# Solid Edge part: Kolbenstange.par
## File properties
Username: bmolnar
Dokumentum tartalom típus: 0
Author: bmolnar
Last saved by: bmolnar
Revision: 77
Sűrűség: 0,000 kg/m^3
Pontosság: 0,990
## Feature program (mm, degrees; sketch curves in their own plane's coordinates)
base feature "unnamed BaseFeature 1"
sketch for "unnamed Protrusion 1" plane through (30, 0, 0) normal (1, 0, 0) x-axis (0, -1, 0)
  circle centre (0, 0) radius 31.5
extrude "unnamed Protrusion 1" add finite 18.25 along +normal
sketch for "Kihúzás_2" plane through (30, 0, 0) normal (1, 0, 0) x-axis (0, -1, 0)
  circle centre (0, 0) radius 31.5
extrude "Kihúzás_2" add finite 3.25 along -normal
sketch for "Furat_1" plane through (0, 0, 0) normal (-1, 0, 0) x-axis (0, 0, -1)
  hole centre (0, 0) bore radius 4.188
hole "Furat_1" nominal diameter 10 finite  ThreadDepth = 17 mm
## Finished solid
Body 1: solid body, 14 faces, 20 edges, 8 vertices.
  Faces by surface: plane 8, cylinder 4, cone 1, torus 1
  Edges by curve: circle 10, line 6, ellipse 2, intersection 2
Bounding box of the edges (mm; curved faces can reach further): 48.250 x 63.000 x 63.000, from (0, -31.5, -31.5) to (48.25, 31.5, 31.5).
Cylindrical faces by radius (mm): R4.188 x2, R8 x1, R31.5 x1
Conical faces (half-angle, radius in mm at the cone's reference point): 45 deg R4.538 x1
Toroidal faces (ring radius, tube radius in mm): R6.3 r1.7 x1
Planar faces by outward normal: +x 1, +z 1, -x 3, -z 1, oblique 2
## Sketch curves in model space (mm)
circle centre (30, 0, 0) radius 31.5
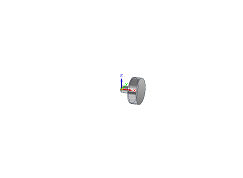
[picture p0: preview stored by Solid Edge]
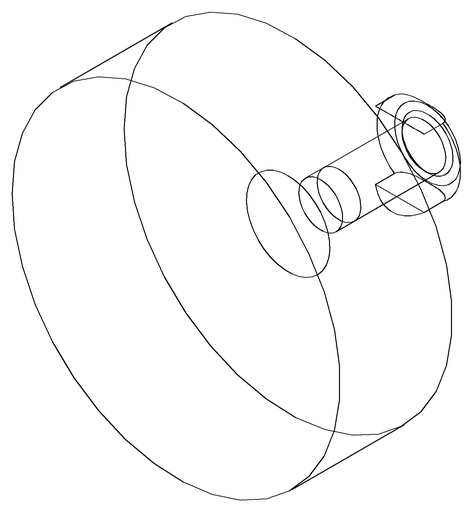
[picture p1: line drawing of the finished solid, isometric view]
